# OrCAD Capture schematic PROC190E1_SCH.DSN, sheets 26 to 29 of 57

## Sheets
26 24. HYPERRAM INTERFACE: size C; title: HYPERRAM INTERFACE
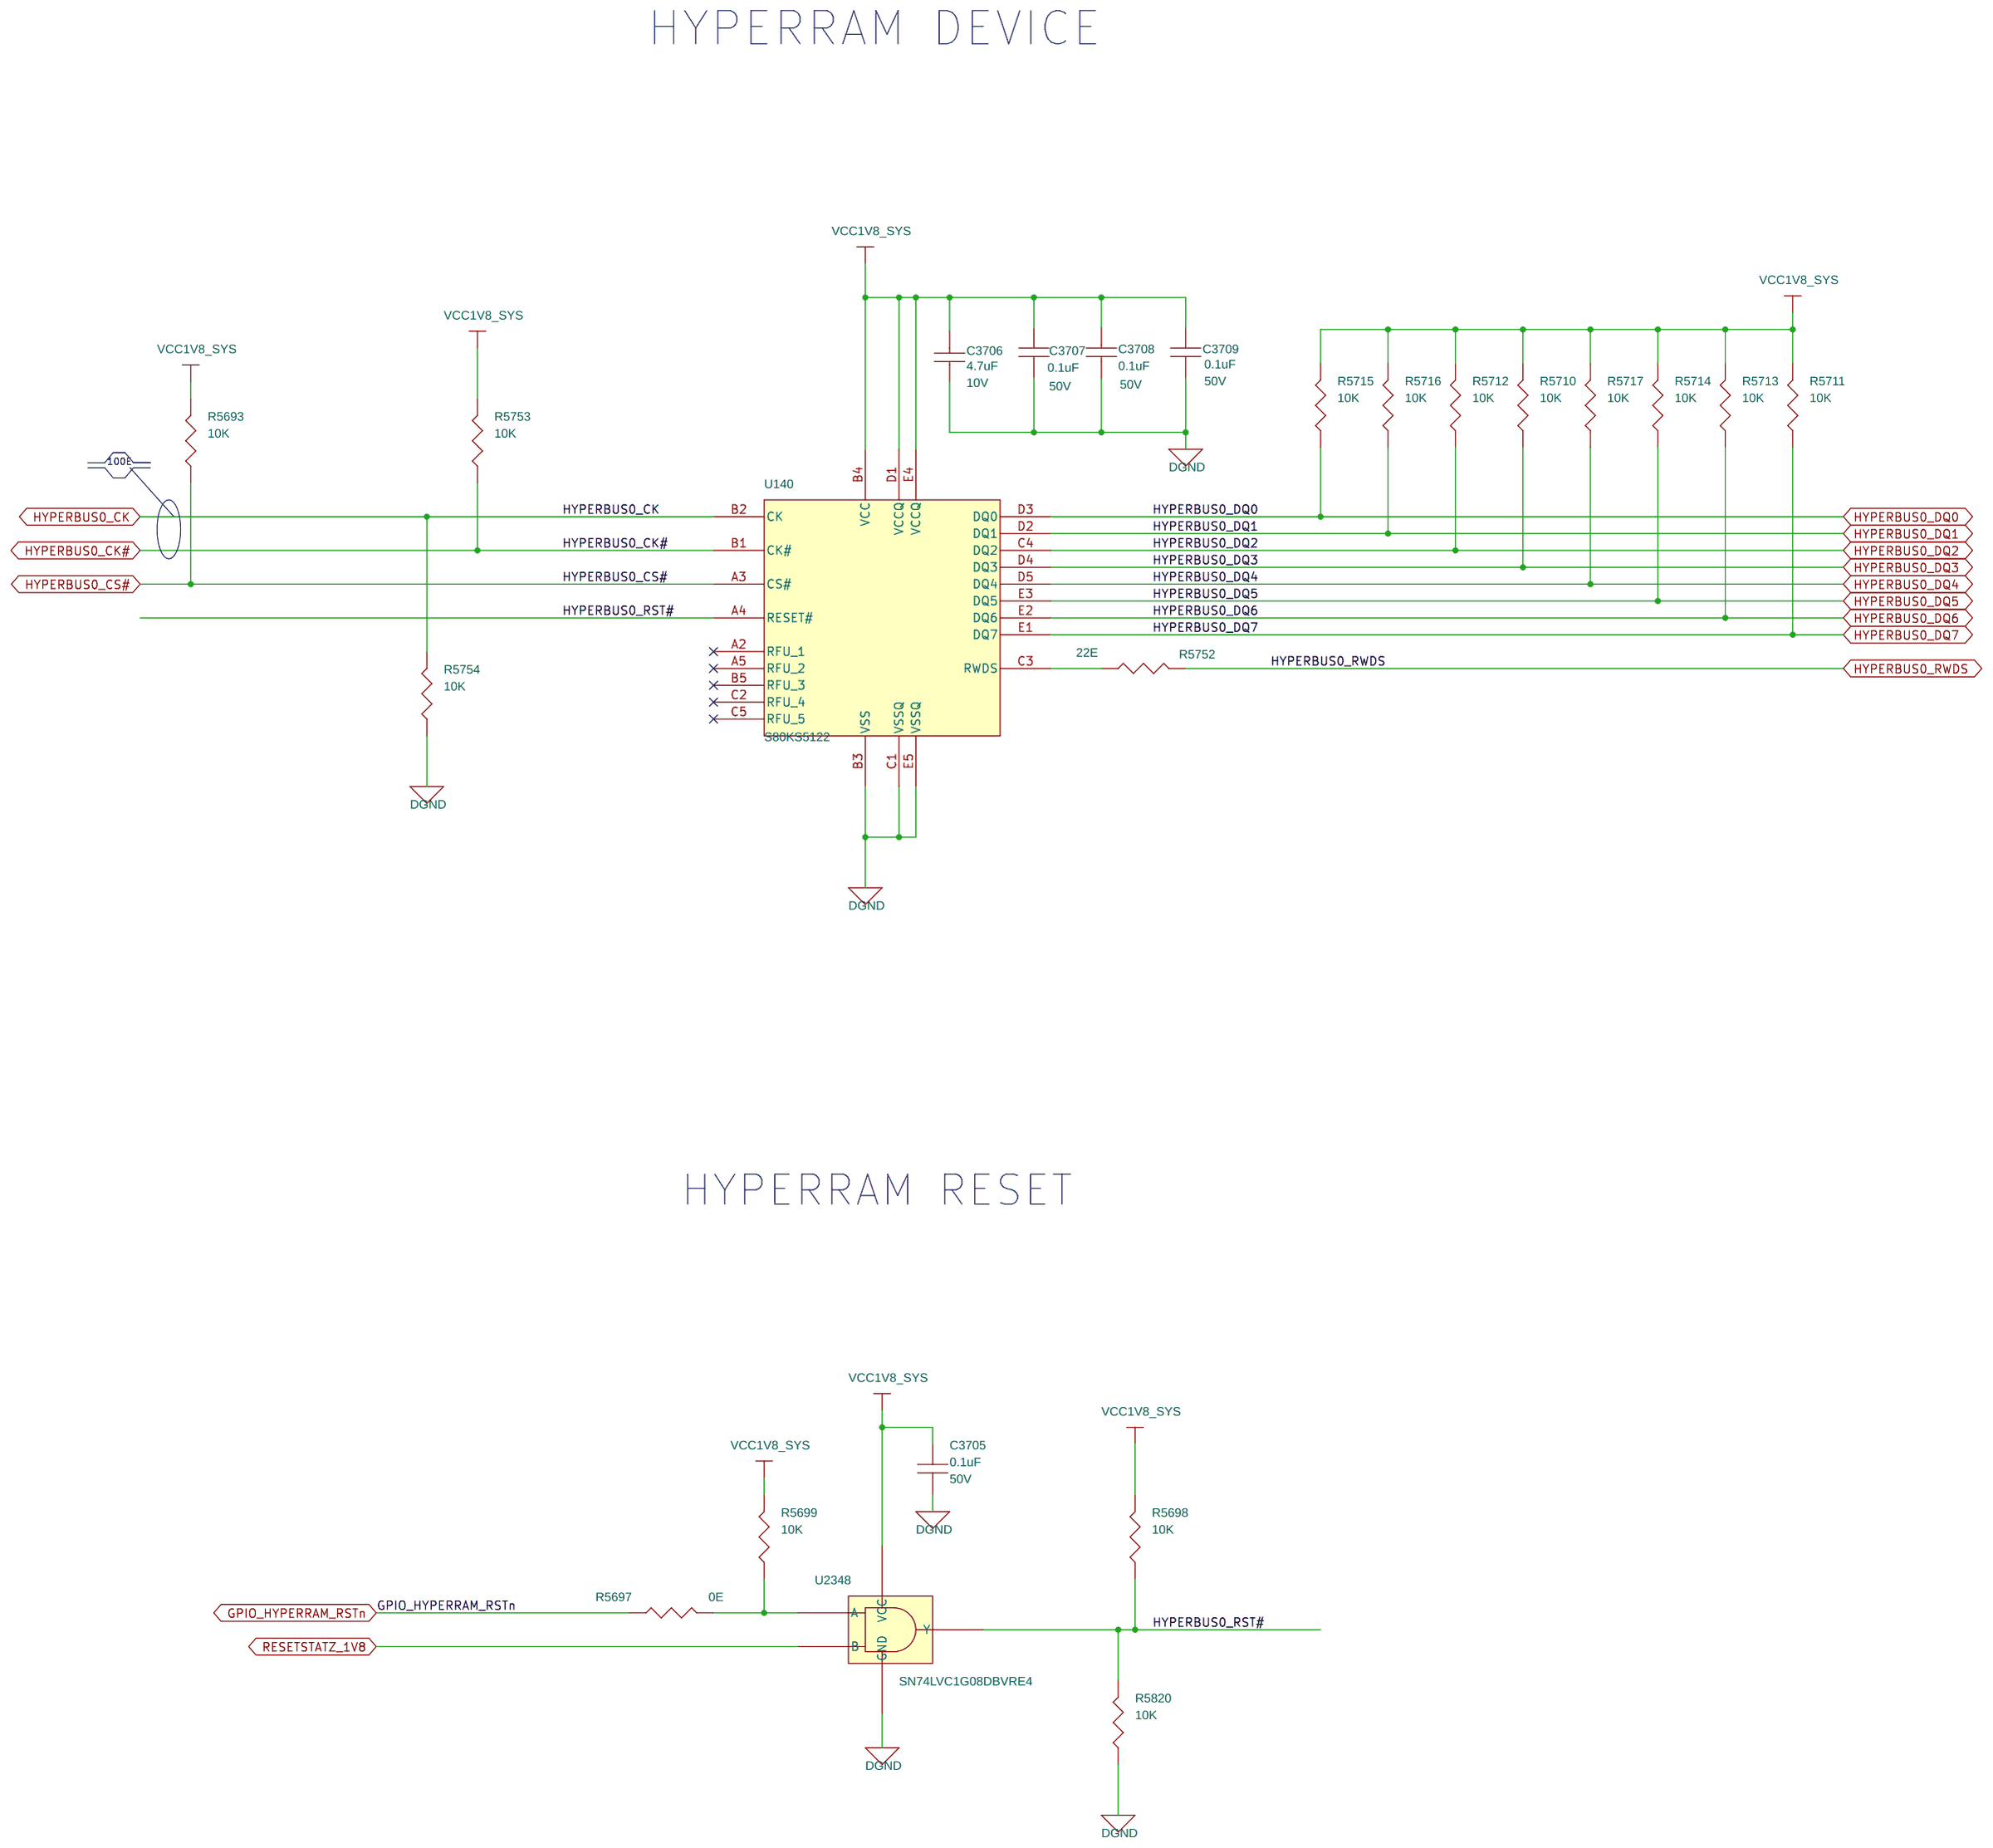
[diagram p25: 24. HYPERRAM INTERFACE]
27 25. OSPI INTERFACE: size C; title: OSPI INTERFACE
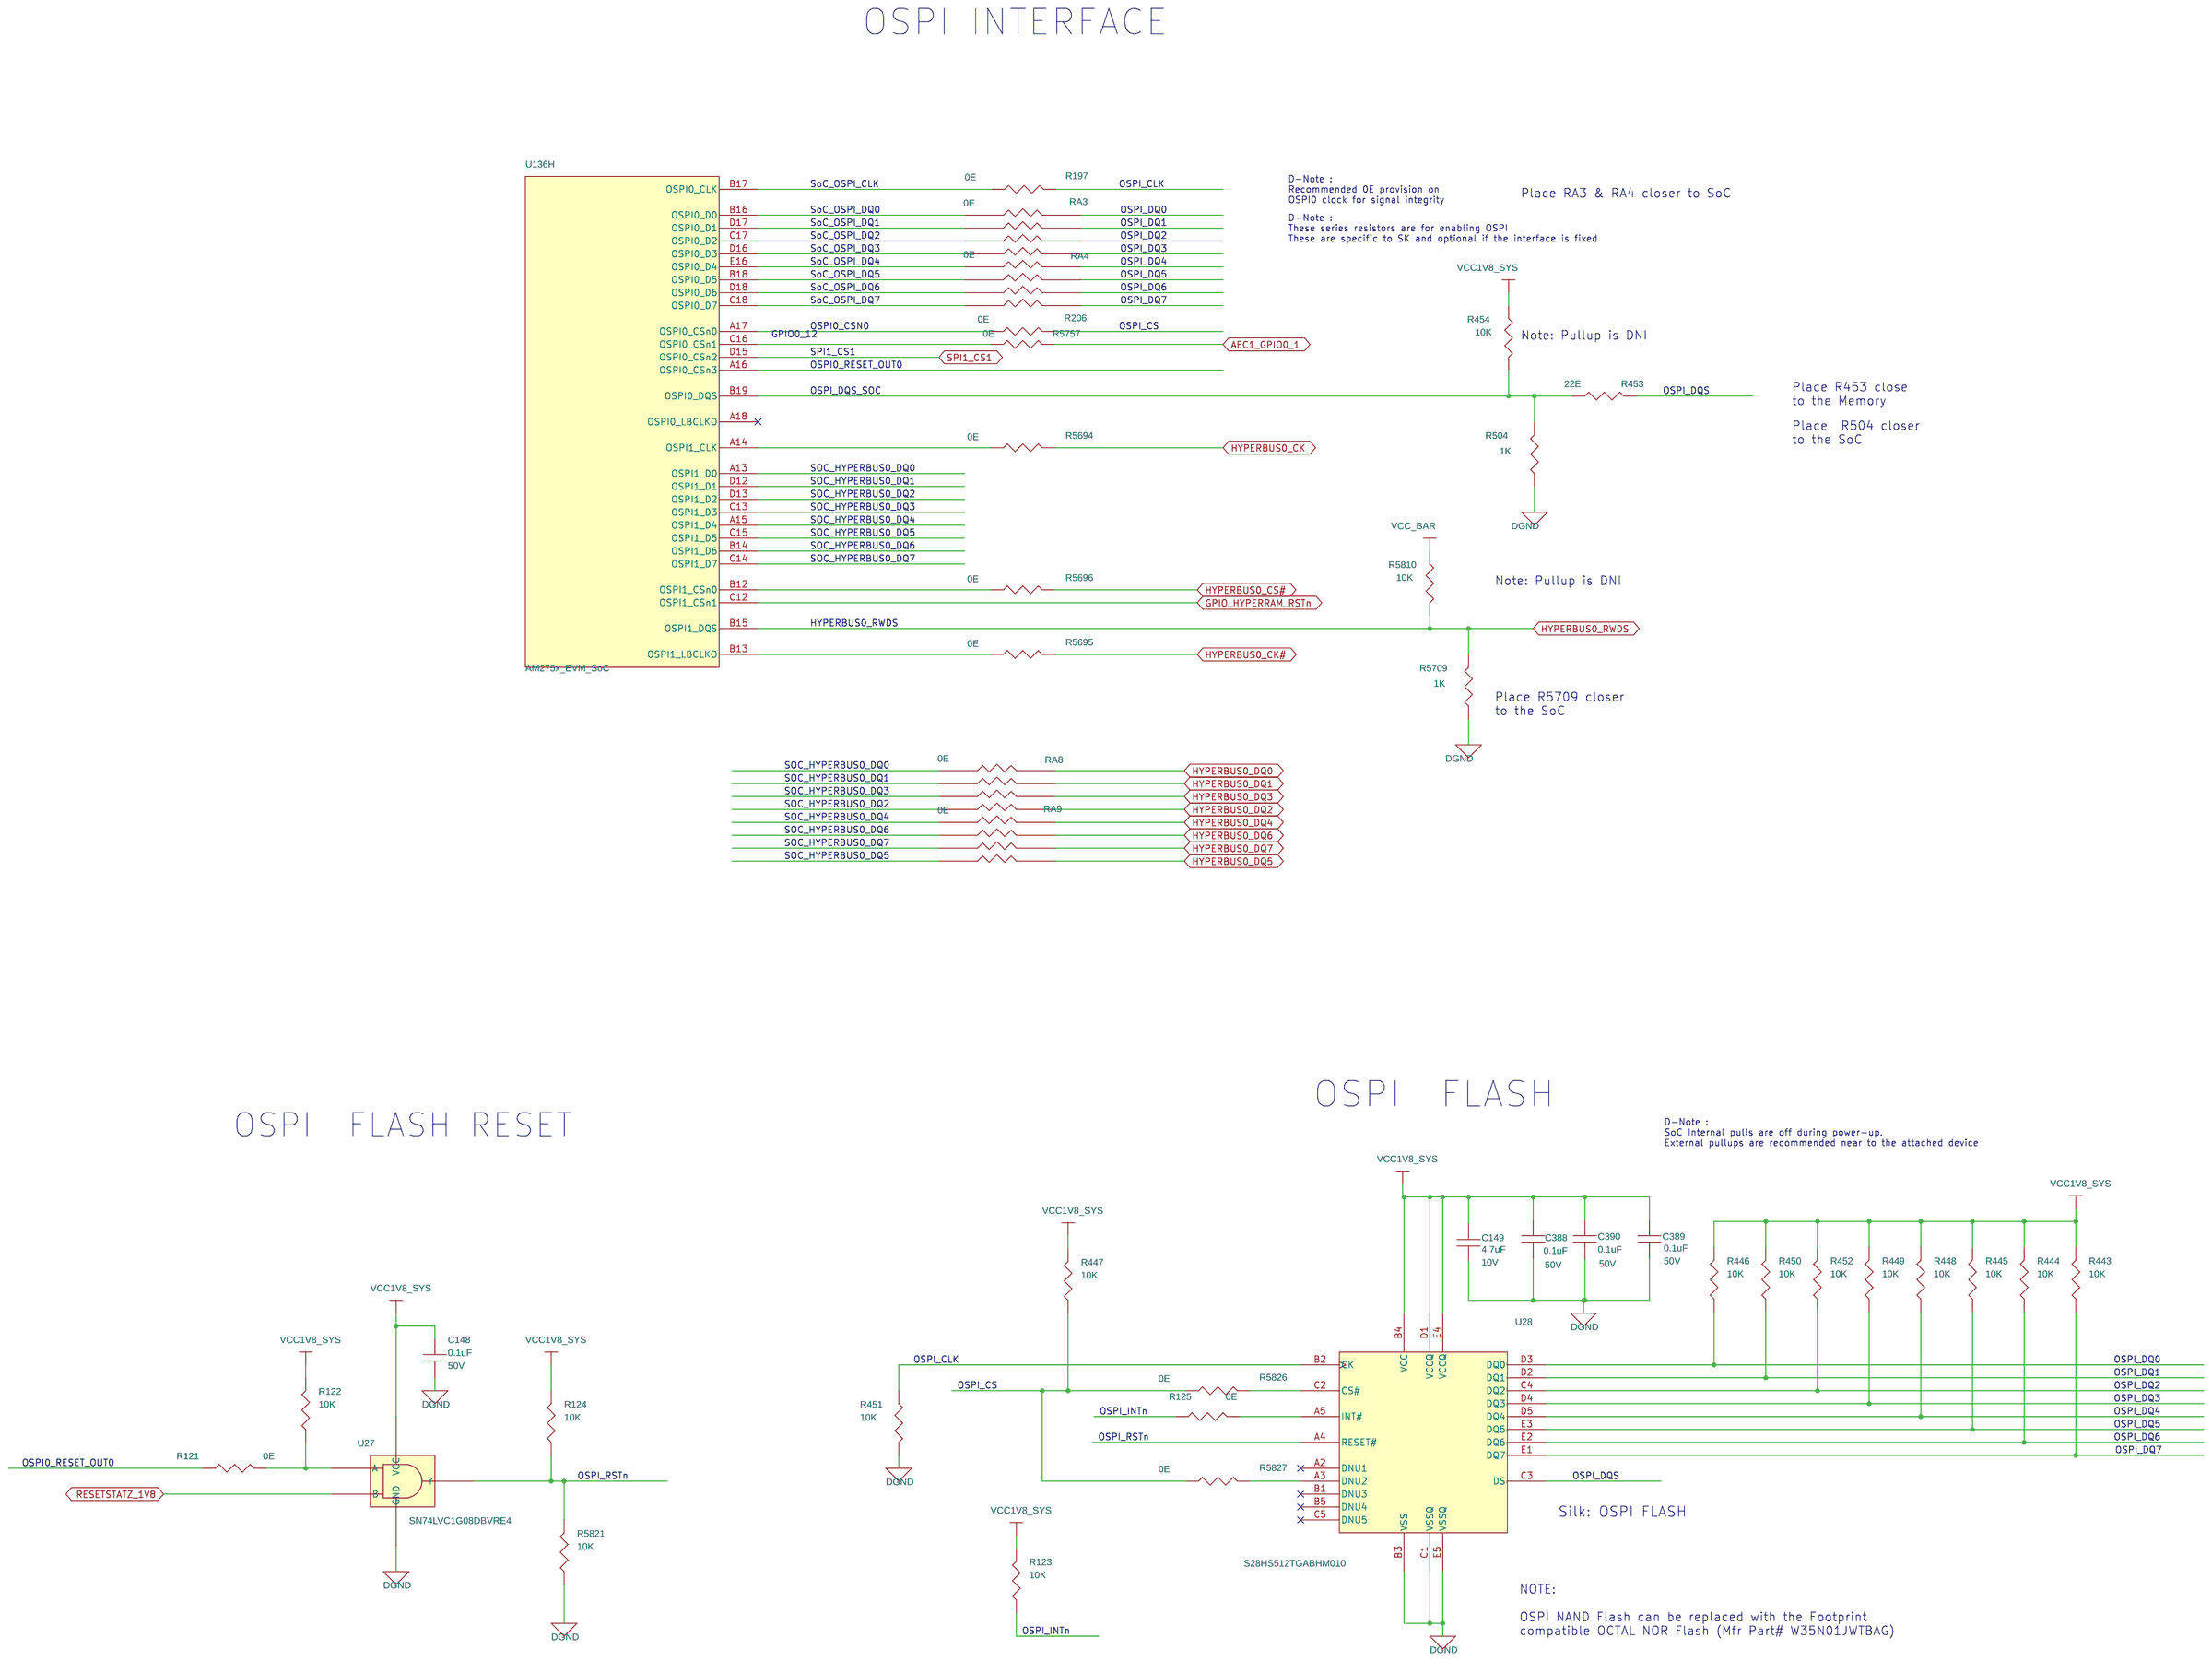
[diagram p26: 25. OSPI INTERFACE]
28 27. eMMC FLASH INTERFACE: size C; title: eMMC  FLASH AND RESET
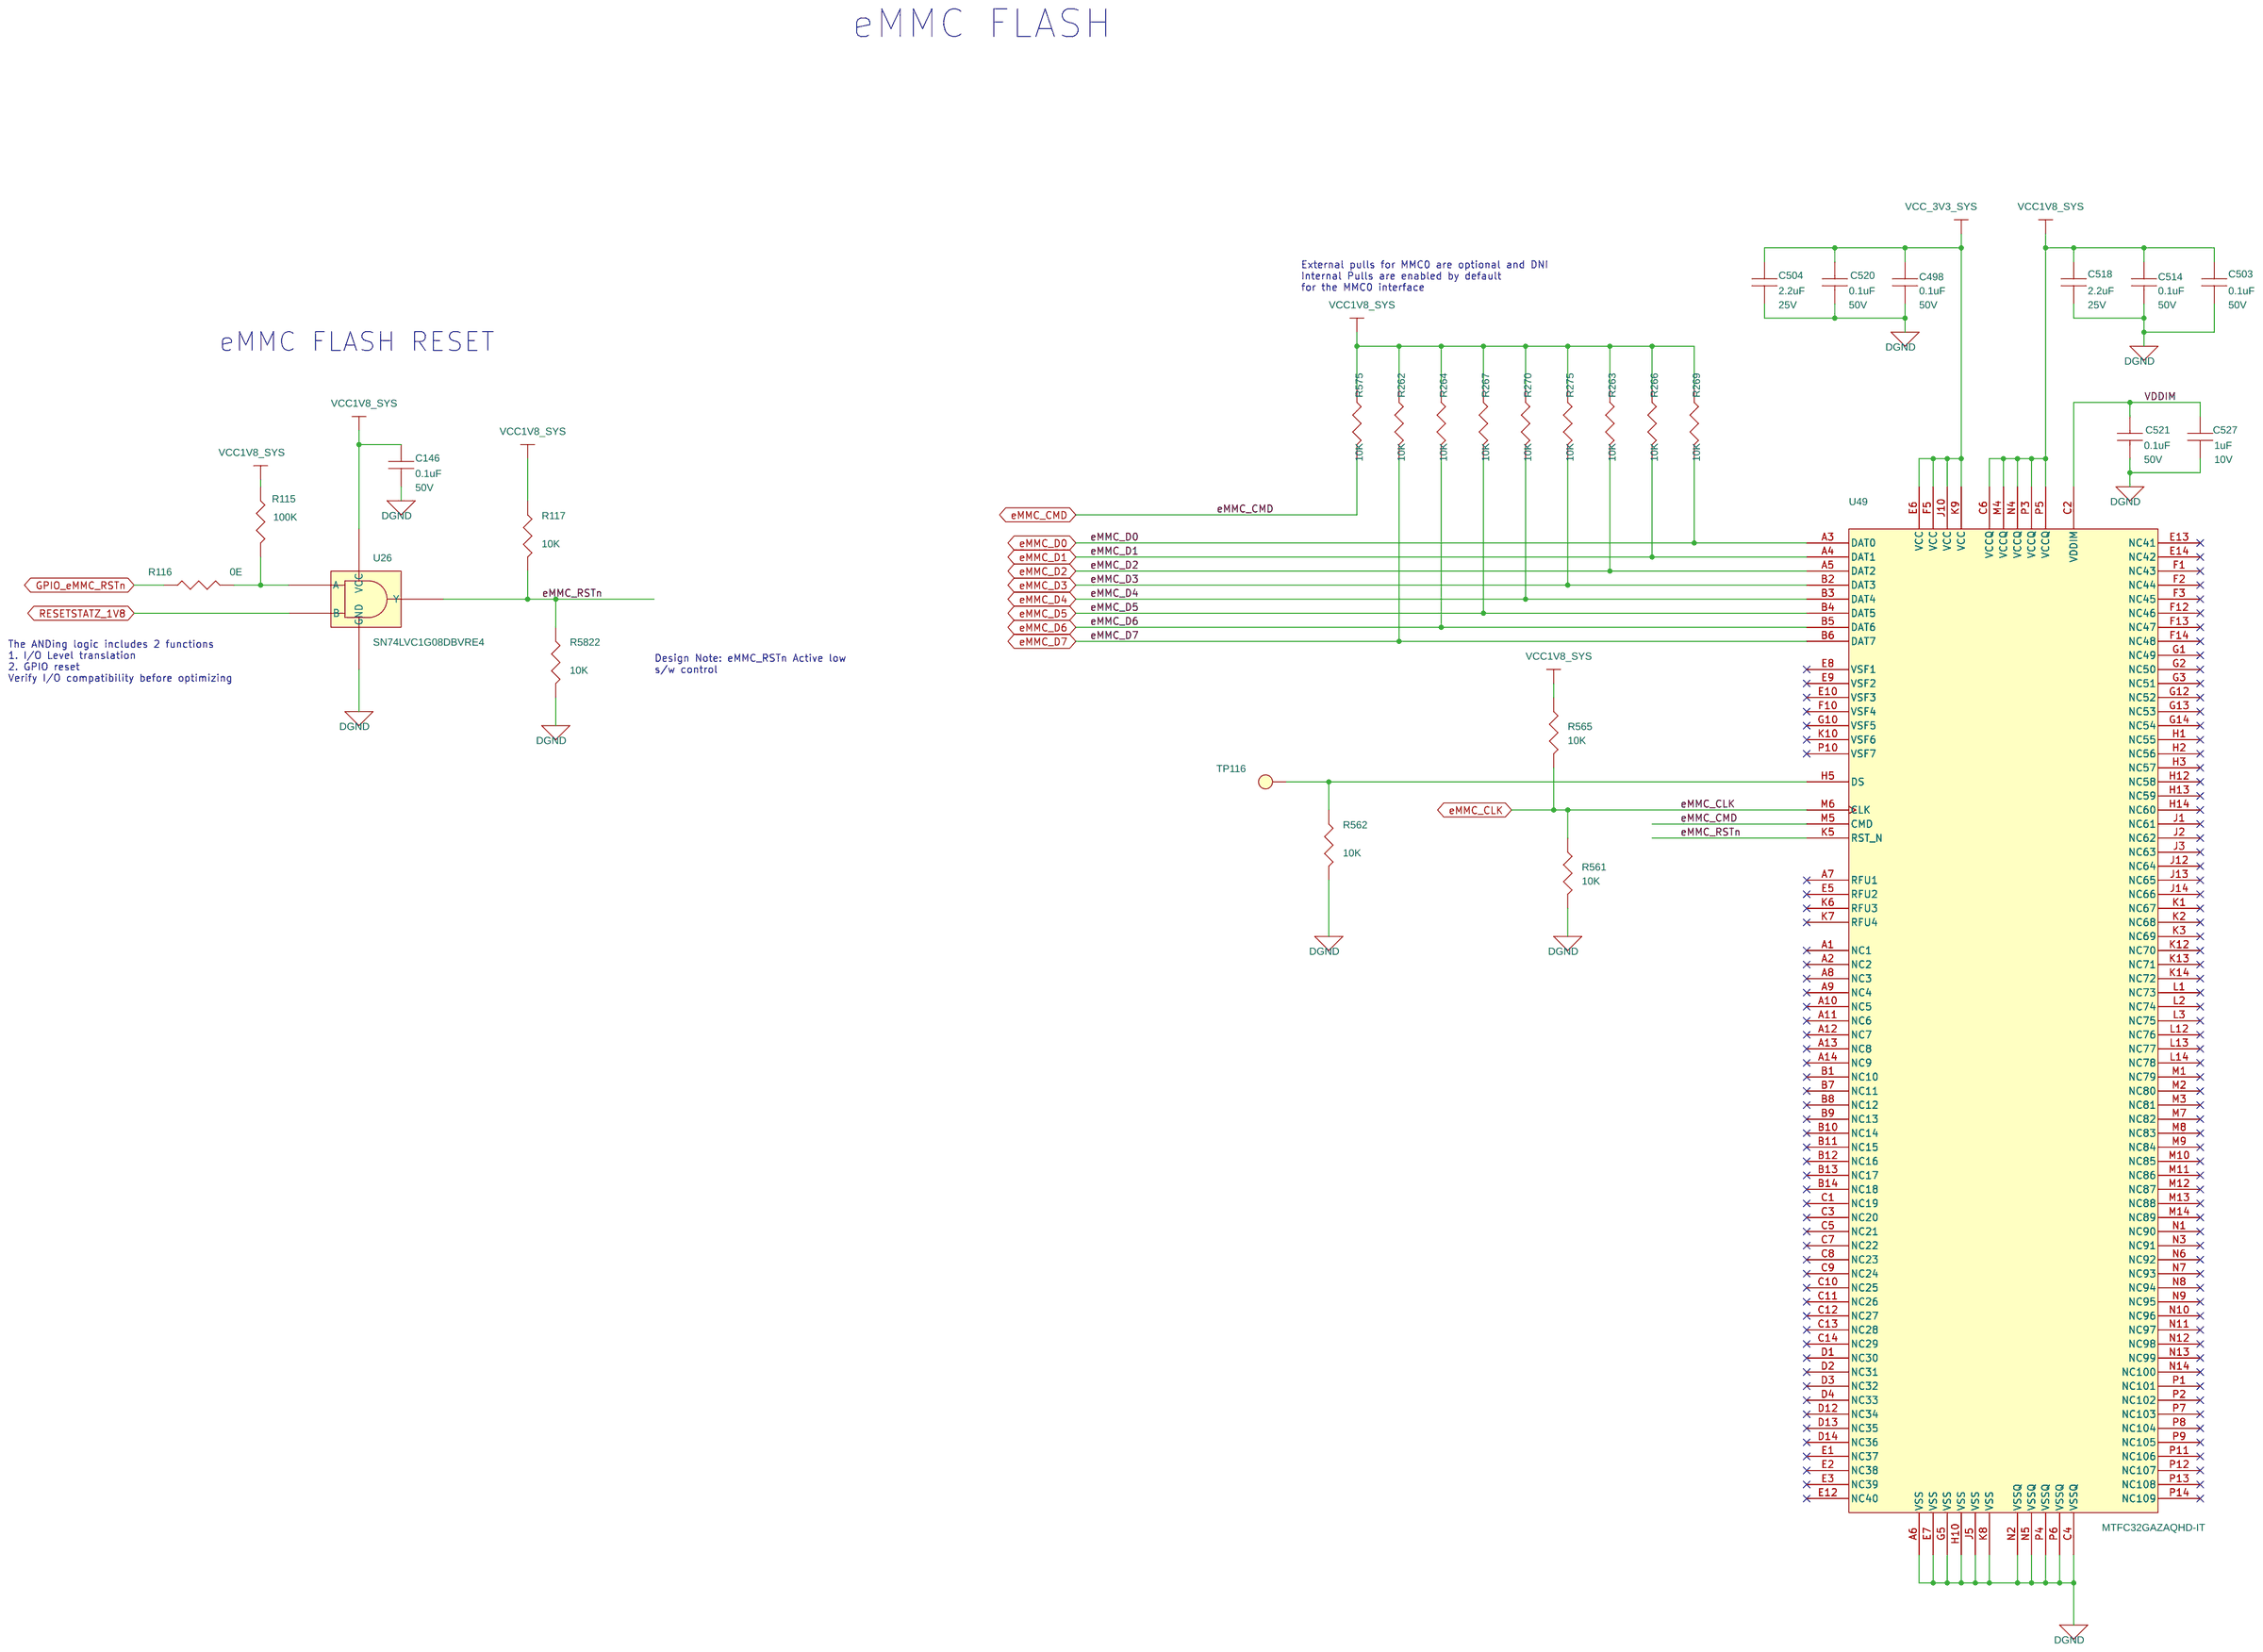
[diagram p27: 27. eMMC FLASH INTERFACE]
29 28. SD CARD INTERFACE: size C; title: SD CARD INTERFACE
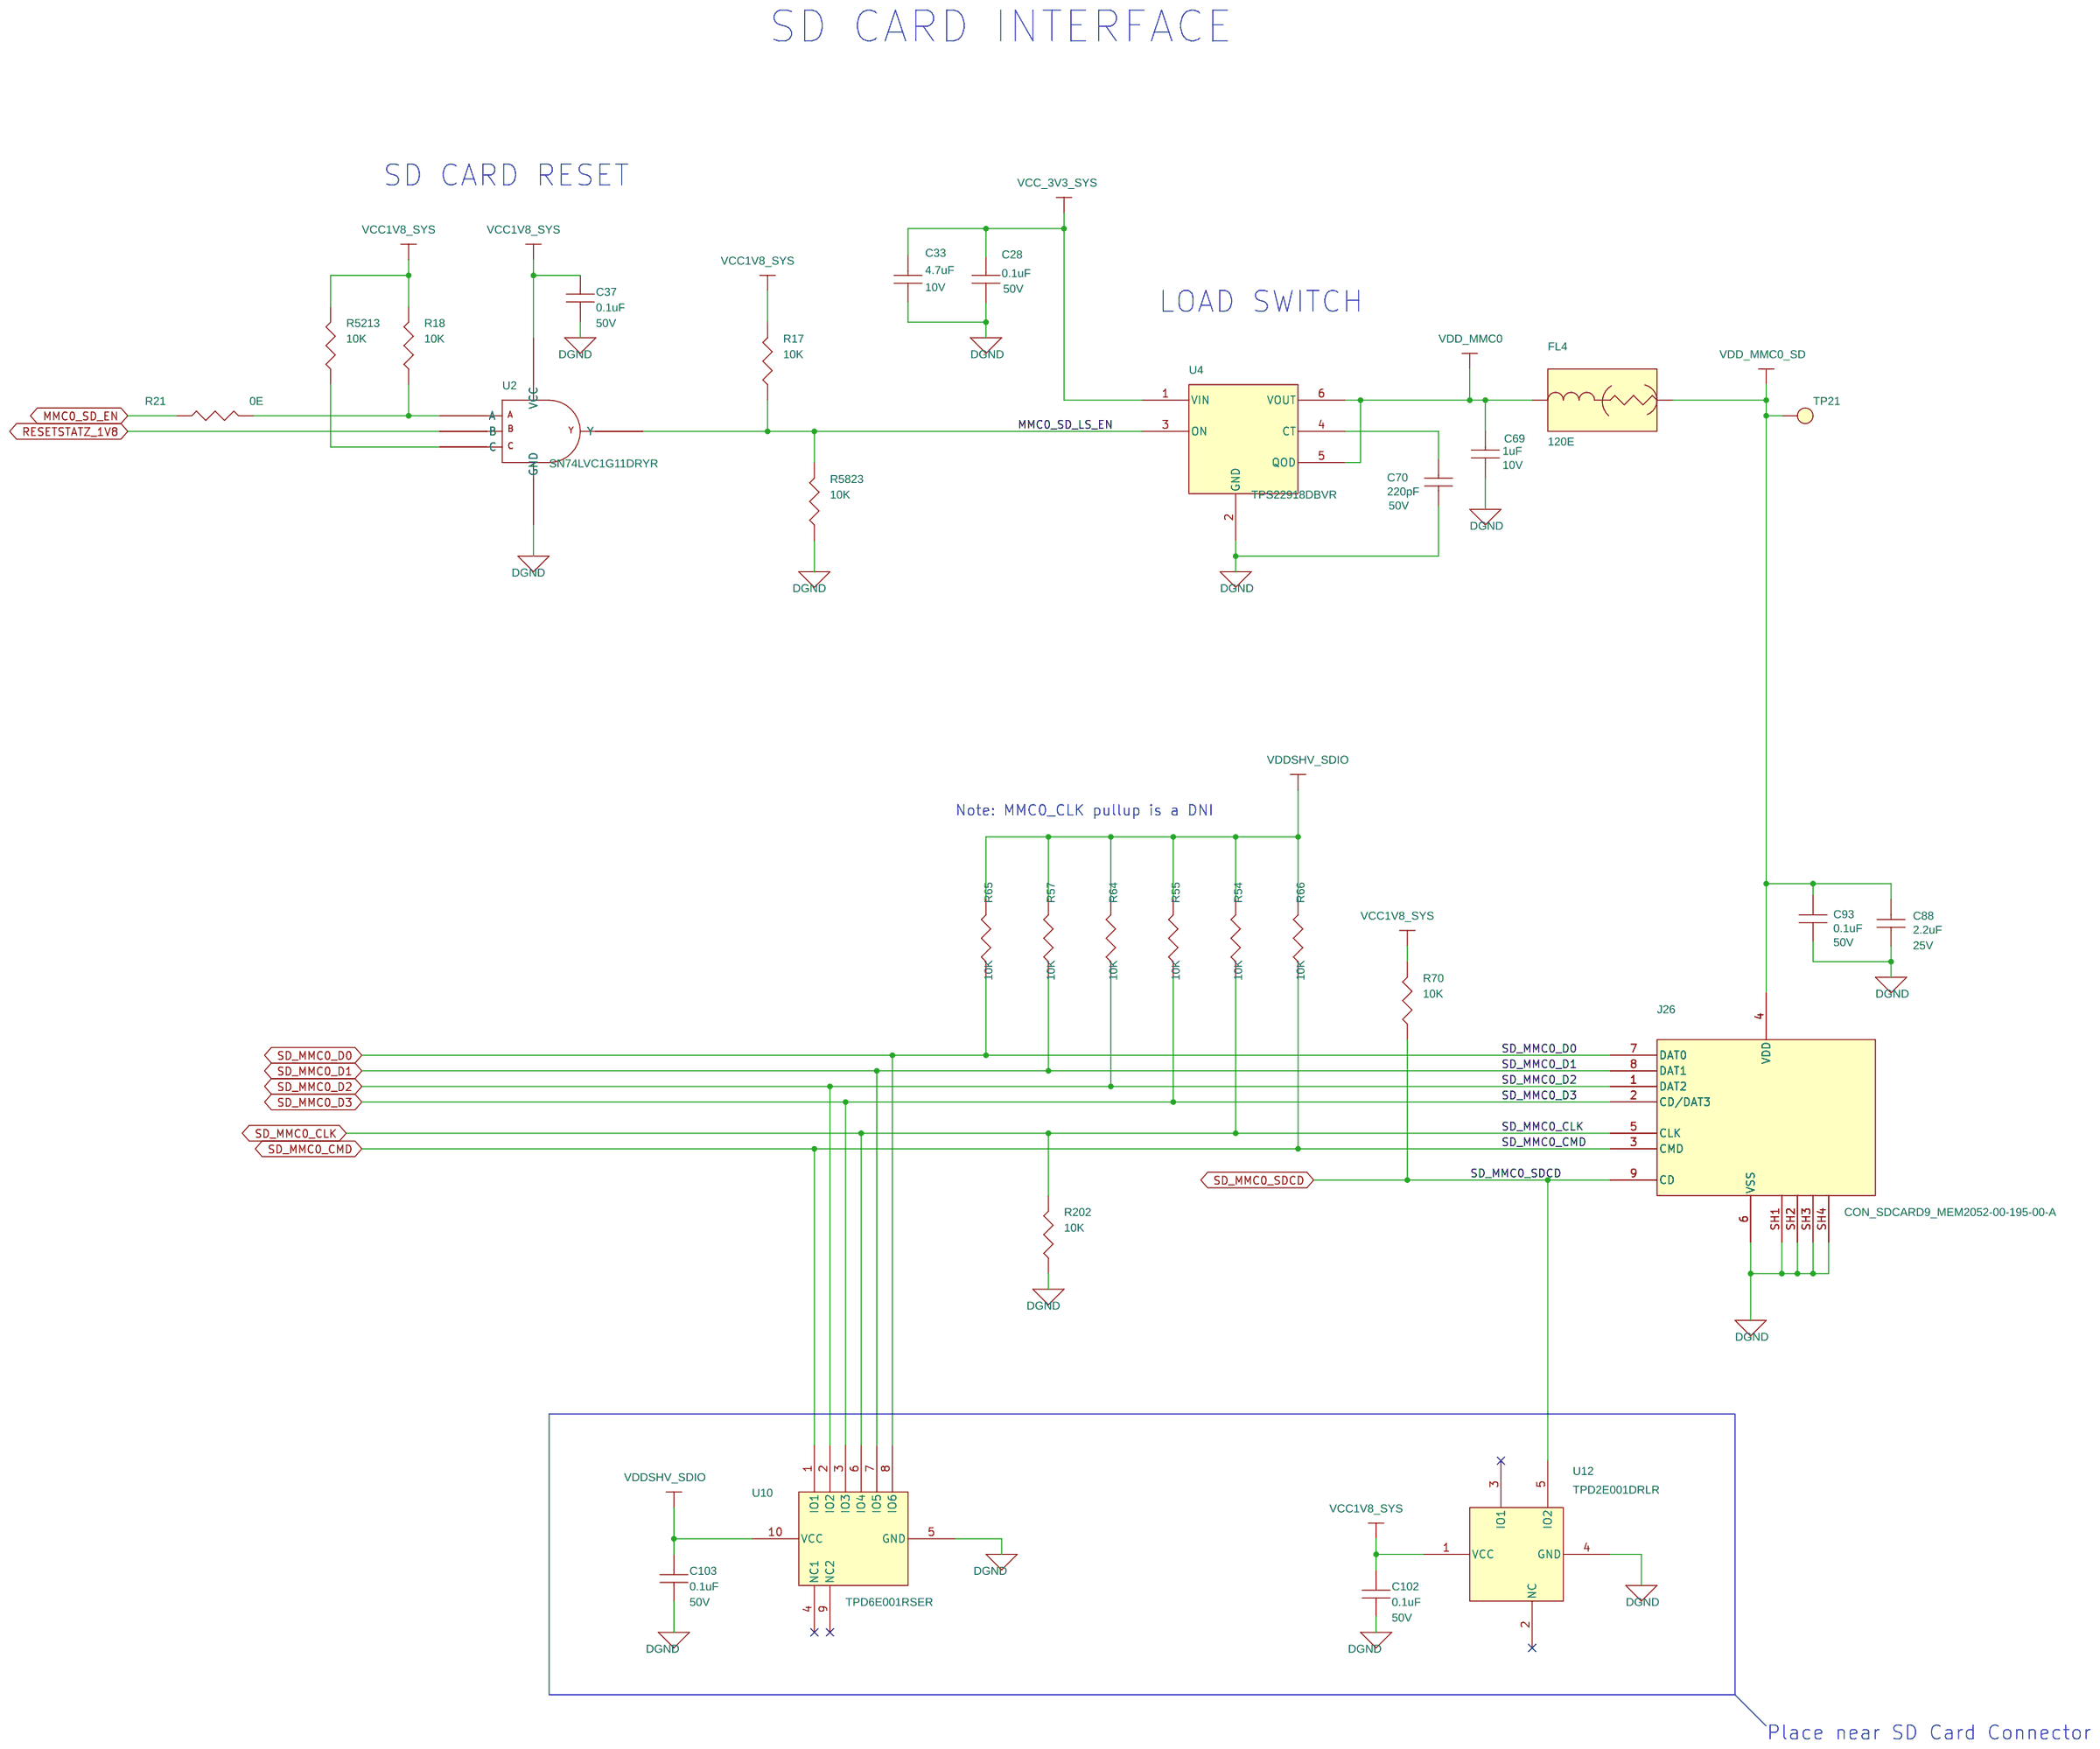
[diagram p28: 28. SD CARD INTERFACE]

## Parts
sheet 19. SOC WKUP & OSC
U136  AM275x_EVM_SoC  [BGA361_31-49_630X630_1-5]  (sections A,B,C,D,E,F,G,H,I,J,K,L,M,N)
sheet 24. HYPERRAM INTERFACE
C3705  0.1uF  [CAP0402_0-75]
C3706  4.7uF  [CAP0402_0-75]
C3707  0.1uF  [CAP0402_0-75]
C3708  0.1uF  [CAP0402_0-75]
C3709  0.1uF  [CAP0402_0-75]
R5693  10K  [RES0201_0-5]
R5697  0E  [RES0201_0-5]
R5698  10K  [RES0201_0-5]
R5699  10K  [RES0201_0-5]
R5710  10K  [RES0201_0-5]
R5711  10K  [RES0201_0-5]
R5712  10K  [RES0201_0-5]
R5713  10K  [RES0201_0-5]
R5714  10K  [RES0201_0-5]
R5715  10K  [RES0201_0-5]
R5716  10K  [RES0201_0-5]
R5717  10K  [RES0201_0-5]
R5752  22E  [RES0402_0-5]
R5753  10K  [RES0201_0-5]
R5754  10K  [RES0201_0-5]
R5820  10K  [RES0201_0-5]
U140  S80KS5122  [BGA24_39-37_240X310_1]
U2348  SN74LVC1G08DBVRE4  [SOT23-5]
sheet 25. OSPI INTERFACE
C148  0.1uF  [CAP0402_0-75]
C149  4.7uF  [CAP0402_0-75]
C388  0.1uF  [CAP0402_0-75]
C389  0.1uF  [CAP0402_0-75]
C390  0.1uF  [CAP0402_0-75]
R121  0E  [RES0201_0-5]
R122  10K  [RES0201_0-5]
R123  10K  [RES0201_0-5]
R124  10K  [RES0201_0-5]
R125  0E  [RES0201_0-5]
R197  0E  [RES0402_0-5]
R206  0E  [RES0402_0-5]
R443  10K  [RES0201_0-5]
R444  10K  [RES0201_0-5]
R445  10K  [RES0201_0-5]
R446  10K  [RES0201_0-5]
R447  10K  [RES0201_0-5]
R448  10K  [RES0201_0-5]
R449  10K  [RES0201_0-5]
R450  10K  [RES0201_0-5]
R451  10K  [RES0201_0-5]
R452  10K  [RES0201_0-5]
R453  22E  [RES0201_0-5]
R454  10K  [RES0201_0-5]
R504  1K  [RES0402_0-5]
R5694  0E  [RES0201_0-5]
R5695  0E  [RES0201_0-5]
R5696  0E  [RES0201_0-5]
R5709  1K  [RES0402_0-5]
R5757  0E  [RES0402_0-5]
R5810  10K  [RES0201_0-5]
R5821  10K  [RES0201_0-5]
R5826  0E  [RES0402_0-5]
R5827  0E  [RES0402_0-5]
RA3  0E  [RESA_EXB_0201-4_0-5]
RA4  0E  [RESA_EXB_0201-4_0-5]
RA8  0E  [RESA_EXB_0201-4_0-5]
RA9  0E  [RESA_EXB_0201-4_0-5]
U27  SN74LVC1G08DBVRE4  [SOT23-5]
U28  S28HS512TGABHM010  [BGA24_39-37_240X310_1]
sheet 27. eMMC FLASH INTERFACE
C146  0.1uF  [CAP0402_0-75]
C498  0.1uF  [CAP0402_0-75]
C503  0.1uF  [CAP0402_0-75]
C504  2.2uF  [CAP0402_0-75]
C514  0.1uF  [CAP0402_0-75]
C518  2.2uF  [CAP0402_0-75]
C520  0.1uF  [CAP0402_0-75]
C521  0.1uF  [CAP0402_0-75]
C527  1uF  [CAP0201_0-5]
R115  100K  [RES0201_0-5]
R116  0E  [RES0201_0-5]
R117  10K  [RES0201_0-5]
R262  10K  [RES0201_0-5]
R263  10K  [RES0201_0-5]
R264  10K  [RES0201_0-5]
R266  10K  [RES0201_0-5]
R267  10K  [RES0201_0-5]
R269  10K  [RES0201_0-5]
R270  10K  [RES0201_0-5]
R275  10K  [RES0201_0-5]
R561  10K  [RES0201_0-5]
R562  10K  [RES0201_0-5]
R565  10K  [RES0201_0-5]
R575  10K  [RES0201_0-5]
R5822  10K  [RES0201_0-5]
TP116  TP20_SMD  [TP20_SMD]
U26  SN74LVC1G08DBVRE4  [SOT23-5]
U49  MTFC32GAZAQHD-IT  [VFBGA153_19-68_460X520_0-9]
sheet 28. SD CARD INTERFACE
C28  0.1uF  [CAP0402_0-75]
C33  4.7uF  [CAP0402_0-75]
C37  0.1uF  [CAP0402_0-75]
C69  1uF  [CAP0201_0-5]
C70  220pF  [CAP0402_0-75]
C88  2.2uF  [CAP0402_0-75]
C93  0.1uF  [CAP0402_0-75]
C102  0.1uF  [CAP0402_0-75]
C103  0.1uF  [CAP0402_0-75]
FL4  120E  [EMIFIL_BLM15A_0402_0-6]
J26  CON_SDCARD9_MEM2052-00-195-00-A  [CON_SD9_MEM2052-00-195-00_S_R_S_2]
R17  10K  [RES0201_0-5]
R18  10K  [RES0201_0-5]
R21  0E  [RES0201_0-5]
R54  10K  [RES0201_0-5]
R55  10K  [RES0201_0-5]
R57  10K  [RES0201_0-5]
R64  10K  [RES0201_0-5]
R65  10K  [RES0201_0-5]
R66  10K  [RES0201_0-5]
R70  10K  [RES0201_0-5]
R202  10K  [RES0201_0-5]
R5213  10K  [RES0201_0-5]
R5823  10K  [RES0201_0-5]
TP21  TP20_SMD  [TP20_SMD]
U2  SN74LVC1G11DRYR  [SON6_SN74LVC2G17_40X60_0-6]
U4  TPS22918DBVR  [SOT23-6]
U10  TPD6E001RSER  [UQFN10_19-68_80X60_0-6]
U12  TPD2E001DRLR  [SOT553-5_0-6]

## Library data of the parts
U136 = AM275X_EVM_SOC_BGA361: IC AM275x EVM SoC BGA361; Chkd/date: PRADEEP/220524; Crtd /date: SHANKARI/210524; Custom_Duty: NA; Customs_HS_Code: NA; Distributor_name: NA; Distributor_part_number: NA; Height: 1.42MM; Library Ref: AM275x_EVM_SoC_BGA361; Mfr_name: NA; Mistral Part No: 141324050006; Package: BGA361; Part_type: ICS\DIGITAL\FPGA; Project: AM275x_EVM; Remarks: FP NEED TO CHECK WITH MANUFACTURE AND CUSTOMER; RoHS: NA; Temperature: NA; Tolerance: NA; Voltage: NA; Wattage: NA; Weight: NA; Datasheet: Y:\MIS_DATABASE\DATASHEETS\ICS\INTERFACE\AM275x_EVM_SoC.PDF
C28 C37 C93 C102 C103 C146 C148 C388-C390 C498 C503 C514 C520 C521 C3705 C3707-C3709 = CAP: CAP CERAMIC 0.1uF 50V 10% X7R AUTO 0402; Alt_Mfr_name: YAGEO AMERICA; Alt_Mfr_part_number: CC0402KRX5R8BB104; Chkd/date: MANIRAJA/250221; Crtd /date: ALVY/240221; Custom_Duty: 15%; Customs_HS_Code: 85322990; Distributor_name: MOUSER; Distributor_part_number: 81-GRT155R71H104KE1D; Footprint Path: Y:\MIS_DATABASE\Library\ALTIUM_TOOL\PCB_FOOTPRINTS\Altium_Footprint_Lib.PcbLib; Height: 0.55MM; Library Path: Y:\MIS_DATABASE\Library\ALTIUM_TOOL\SCHEMATICS_PARTS\MS_DISCRETE_Library.schlib; Mfr_name: MURATA; Mfr_part_number: GRT155R71H104KE01D; Mistral Part No: 120019030005-R; Package: 0402; Part_type: CAPACITORS\CERAMIC; Project: TI_DRA821 SK EVM BRD; RoHS: RoHS; Temperature: -55°C+125°C; Tolerance: 10%; Voltage: 50V; Wattage: NA; Weight: NA; Datasheet: Y:\MIS_DATABASE\DATASHEETS\CAPACITORS\GRT155R71H104KE01.PDF
C33 C149 C3706 = CAP: CAP CERAMIC 4.7uF 10V 20% X5R AUTO 0402; Chkd/date: MANIRAJA/250221; Crtd /date: ALVY/240221; Custom_Duty: 15%; Customs_HS_Code: 85322990; Distributor_name: MOUSER; Distributor_part_number: 81-GRT155R61A475ME13; Footprint Path: Y:\MIS_DATABASE\Library\ALTIUM_TOOL\PCB_FOOTPRINTS\Altium_Footprint_Lib.PcbLib; Height: 0.65MM; Library Path: Y:\MIS_DATABASE\Library\ALTIUM_TOOL\SCHEMATICS_PARTS\MS_DISCRETE_Library.schlib; Mfr_name: MURATA; Mfr_part_number: GRT155R61A475ME13D; Mistral Part No: 120021020032-R; Package: 0402; Part_type: CAPACITORS\CERAMIC; Project: TI_DRA821 SK EVM BRD; RoHS: RoHS; Temperature: -55°C+85°C; Tolerance: 20%; Voltage: 10V; Wattage: NA; Weight: 1.5mg; Datasheet: Y:\MIS_DATABASE\DATASHEETS\CAPACITORS\GRT155R61A475ME13.PDF
R17 R18 R54 R55 R57 R64-R66 R70 R117 R122-R124 R202 R262-R264 R266 R267 R269 R270 R275 R443-R452 R454 R561 R562 R565 R575 R5213 R5693 R5698 R5699 R5710-R5717 R5753 R5754 R5810 R5820-R5823 = RESISTOR: RES 10K 1/20W 5% 0201; Chkd/date: MANIRAJA/050517; Crtd /date: MANIRAJA/050517; Custom_Duty: 15%; Customs_HS_Code: 85332119; Distributor_name: DIGIKEY; Distributor_part_number: 311-10KNCT-ND; Footprint Path: Y:\MIS_DATABASE\Library\ALTIUM_TOOL\PCB_FOOTPRINTS\Altium_Footprint_Lib.PcbLib; Height: 0.26MM; Library Path: Y:\MIS_DATABASE\Library\ALTIUM_TOOL\SCHEMATICS_PARTS\MS_DISCRETE_Library.schlib; Mfr_name: YAGEO AMERICA; Mfr_part_number: RC0201JR-0710KL; Mistral Part No: 110010070051-R; Package: 0201; Part_type: RESISTORS\FIXED; Project: GOLDEN-I LITE; RoHS: RoHS; Temperature: -55°C+125°C; Tolerance: 5%; Voltage: NA; Wattage: 1/20W; Weight: 0.17mg; Datasheet: Y:\MIS_DATABASE\DATASHEETS\RESISTORS\RCXXXXL-SER_MAR18.PDF
R21 R116 R121 R125 R5697 = RESISTOR: RES 0E 1/20W 5% 0201; Chkd/date: NAVEED/301214; Crtd /date: MUDDU/120710; Custom_Duty: 15%; Customs_HS_Code: 85332119; Distributor_name: DIGIKEY; Distributor_part_number: 311-0.0NCT-ND; Footprint Path: Y:\MIS_DATABASE\Library\ALTIUM_TOOL\PCB_FOOTPRINTS\Altium_Footprint_Lib.PcbLib; Height: 0.26MM; Library Path: Y:\MIS_DATABASE\Library\ALTIUM_TOOL\SCHEMATICS_PARTS\MS_DISCRETE_Library.schlib; Mfr_name: YAGEO AMERICA; Mfr_part_number: RC0201JR-070RL; Mistral Part No: 110010070067-R; Package: 0201; Part_type: RESISTORS\FIXED; Project: PB_BUGBASE; RoHS: RoHS; Temperature: -55°C+125°C; Tolerance: 5%; Voltage: NA; Wattage: 1/20W; Weight: 0.17mg; Datasheet: Y:\MIS_DATABASE\DATASHEETS\RESISTORS\RCXXXXL-SER_MAR18.PDF
R5752 = RESISTOR: RES 22E 1/10W 5% 0402; Chkd/date: VASANTHA/060117; Crtd /date: MAZHAR/120505; Custom_Duty: 15%; Customs_HS_Code: 85332119; Distributor_name: DIGIKEY; Distributor_part_number: P22JCT-ND; Footprint Path: Y:\MIS_DATABASE\Library\ALTIUM_TOOL\PCB_FOOTPRINTS\Altium_Footprint_Lib.PcbLib; Height: 0.40MM; Library Path: Y:\MIS_DATABASE\Library\ALTIUM_TOOL\SCHEMATICS_PARTS\MS_DISCRETE_Library.schlib; Mfr_name: PANASONIC-ECG; Mfr_part_number: ERJ-2GEJ220X; Mistral Part No: 110009030515-R; Package: 0402; Part_type: RESISTORS\FIXED; Project: EPDA_CORE; RoHS: RoHS; Temperature: -55°C+155°C; Tolerance: 5%; Voltage: NA; Wattage: 1/10W; Weight: 0.8mg; Datasheet: Y:\MIS_DATABASE\DATASHEETS\RESISTORS\PAN-ERJSER_NOV17.PDF
U140 = S80KS5122GABHM_BGA24: IC 512MBIT FLASH MEMORY BGA24; Chkd/date: PRADEEP/200524; Crtd /date: SHANKARI/200524; Custom_Duty: 15%; Customs_HS_Code: 85423100; Distributor_name: DIGYKEY; Distributor_part_number: 448-S80KS5122GABHM020-ND; Footprint Path: Y:\MIS_DATABASE\Library\ALTIUM_TOOL\PCB_FOOTPRINTS\Altium_Footprint_Lib.PcbLib; Height: 1.00MM; Library Path: Y:\MIS_DATABASE\Library\ALTIUM_TOOL\SCHEMATICS_PARTS\MS_MISCPOWER_Library.schlib; Mfr_name: INFINEON TECHNOLOGIES; Mfr_part_number: S80KS5122GABHM020; Mistral Part No: 141124050003-R; Package: BGA24; Part_type: ICS\DIGITAL\MEMORY; Project: AM275x_EVM; RoHS: RoHS; Temperature: -40°C+125°C; Tolerance: NA; Voltage: NA; Wattage: NA; Weight: NA; Datasheet: Y:\MIS_DATABASE\DATASHEETS\ICS\INTERFACE\S80KS5122.PDF
U26 U27 U2348 = SN74LVC1G08DBVRE4_SOT23-5: IC SINGLE 2-INPUT POSITIVE AND GATE SOT23-5; Chkd/date: SUHAS/221010; Crtd /date: USMAN/151008; Custom_Duty: 15%; Customs_HS_Code: 85423100; Distributor_name: DIGIKEY; Distributor_part_number: SN74LVC1G08DBVRE4-ND; Height: 1.45MM; Mfr_name: TEXAS INSTRUMENTS; Mistral Part No: 141009060026-R; Part_type: ICS\DIGITAL\GATES; Project: KHAN_MAIN; RoHS: Sb/ Br FREE; Temperature: -40°C+85°C; Datasheet: Y:\MIS_DATABASE\DATASHEETS\ICS\DIGITAL\GATES\SN74LVC1G08.PDF
R197 R206 R5826 R5827 = RESISTOR: RES 0E 1/10W JUMPER 0402; Chkd/date: VASANTHA/061216; Crtd /date: NAVEED/201014; Custom_Duty: 15%; Customs_HS_Code: 85332119; Distributor_name: DIGIKEY; Distributor_part_number: P0.0JCT-ND; Footprint Path: Y:\MIS_DATABASE\Library\ALTIUM_TOOL\PCB_FOOTPRINTS\Altium_Footprint_Lib.PcbLib; Height: 0.40MM; IBISSP_MODLES: VALUE REPEATING 2 TIME; Library Path: Y:\MIS_DATABASE\Library\ALTIUM_TOOL\SCHEMATICS_PARTS\MS_DISCRETE_Library.schlib; Mfr_name: PANASONIC-ECG; Mfr_part_number: ERJ-2GE0R00X; Mistral Part No: 110018030052-R; Package: 0402; Part_type: RESISTORS\FIXED; Project: AEGIS POM; RoHS: RoHS; SIGNAL_MODEL: RESISTOR_RES0402_0-5_0E_0E; Temperature: -55°C+155°C; Tolerance: NA; Voltage: NA; Wattage: 1/10W; Weight: 0.8mg; Datasheet: Y:\MIS_DATABASE\DATASHEETS\RESISTORS\PAN-ERJSER_NOV17.PDF
R453 = RESISTOR: RES 22E 1/20W 5% 0201; Chkd/date: ALVY/210122; Crtd /date: TAMILARASU/210122; Custom_Duty: 15%; Customs_HS_Code: 85332119; Distributor_name: DIGIKEY; Distributor_part_number: 541-22AGCT-ND; Footprint Path: Y:\MIS_DATABASE\Library\ALTIUM_TOOL\PCB_FOOTPRINTS\Altium_Footprint_Lib.PcbLib; Height: 0.28MM; Library Path: Y:\MIS_DATABASE\Library\ALTIUM_TOOL\SCHEMATICS_PARTS\MS_DISCRETE_Library.schlib; Mfr_name: VISHAY; Mfr_part_number: CRCW020122R0JNED; Mistral Part No: 110022010021-R; Package: 0201; Part_type: RESISTORS\FIXED; Project: DLRL DIGITAL RECEIVER_BRD; RoHS: RoHS; SIGNAL_MODEL: RESISTOR_RES0201_0-5_22E_1%_22E_1%; Temperature: -55°C+155°C; Tolerance: 5%; Voltage: NA; Wattage: 1/20W; Weight: 0.17mg; Datasheet: Y:\MIS_DATABASE\DATASHEETS\RESISTORS\CRCW0201.PDF
R504 R5709 = RESISTOR: RES 1K 1/10W 5% 0402; Chkd/date: VASANTHA/201216; Crtd /date: MAZHAR/230805; Custom_Duty: 15%; Customs_HS_Code: 85332119; Distributor_name: DIGIKEY; Distributor_part_number: P1.0KJCT-ND; Footprint Path: Y:\MIS_DATABASE\Library\ALTIUM_TOOL\PCB_FOOTPRINTS\Altium_Footprint_Lib.PcbLib; Height: 0.40MM; Library Path: Y:\MIS_DATABASE\Library\ALTIUM_TOOL\SCHEMATICS_PARTS\MS_DISCRETE_Library.schlib; Mfr_name: PANASONIC-ECG; Mfr_part_number: ERJ-2GEJ102X; Mistral Part No: 110009030400-R; Package: 0402; Part_type: RESISTORS\FIXED; Project: HSE; RoHS: RoHS; Temperature: -55°C+155°C; Tolerance: 5%; Voltage: NA; Wattage: 1/10W; Weight: 0.8mg; Datasheet: Y:\MIS_DATABASE\DATASHEETS\RESISTORS\PAN-ERJSER_NOV17.PDF
R5694-R5696 = RESISTOR: RES 0E 1/20W 5% 0201; Chkd/date: NAVEED/301214; Crtd /date: MUDDU/120710; Custom_Duty: 15%; Customs_HS_Code: 85332119; Distributor_name: DIGIKEY; Distributor_part_number: 311-0.0NCT-ND; Footprint Path: Y:\MIS_DATABASE\Library\ALTIUM_TOOL\PCB_FOOTPRINTS\Altium_Footprint_Lib.PcbLib; Height: 0.26MM; Library Path: Y:\MIS_DATABASE\Library\ALTIUM_TOOL\SCHEMATICS_PARTS\MS_DISCRETE_Library.schlib; Mfr_name: YAGEO AMERICA; Mfr_part_number: RC0201JR-070RL; Mistral Part No: 110010070067-R; Package: 0201; Part_type: RESISTORS\FIXED; Project: PB_BUGBASE; RoHS: RoHS; SIGNAL_MODEL: RESISTOR_RES0201_0-5_0E_0E; Temperature: -55°C+125°C; Tolerance: 5%; Voltage: NA; Wattage: 1/20W; Weight: 0.17mg; Datasheet: Y:\MIS_DATABASE\DATASHEETS\RESISTORS\RCXXXXL-SER_MAR18.PDF
R5757 = RESISTOR: RES 0E 1/10W JUMPER 0402; Chkd/date: VASANTHA/061216; Crtd /date: NAVEED/201014; Custom_Duty: 15%; Customs_HS_Code: 85332119; Distributor_name: DIGIKEY; Distributor_part_number: P0.0JCT-ND; Footprint Path: Y:\MIS_DATABASE\Library\ALTIUM_TOOL\PCB_FOOTPRINTS\Altium_Footprint_Lib.PcbLib; Height: 0.40MM; IBISSP_MODLES: VALUE REPEATING 2 TIME; Library Path: Y:\MIS_DATABASE\Library\ALTIUM_TOOL\SCHEMATICS_PARTS\MS_DISCRETE_Library.schlib; Mfr_name: PANASONIC-ECG; Mfr_part_number: ERJ-2GE0R00X; Mistral Part No: 110018030052-R; Package: 0402; Part_type: RESISTORS\FIXED; Project: AEGIS POM; RoHS: RoHS; SIGNAL_MODEL: RESISTOR_RES0201_0-5_0E_0E; Temperature: -55°C+155°C; Tolerance: NA; Voltage: NA; Wattage: 1/10W; Weight: 0.8mg; Datasheet: Y:\MIS_DATABASE\DATASHEETS\RESISTORS\PAN-ERJSER_NOV17.PDF
RA3 RA4 RA8 RA9 = RESARR_ISO4: RES ARRAY 0E 31mW JUMPER 0201-4; Chkd/date: MANIRAJA/290918; Crtd /date: MANIRAJA/290918; Custom_Duty: 15%; Customs_HS_Code: 85332119; Distributor_name: DIGIKEY; Distributor_part_number: Y6000CT-ND; Footprint Path: Y:\MIS_DATABASE\Library\ALTIUM_TOOL\PCB_FOOTPRINTS\Altium_Footprint_Lib.PcbLib; Height: 0.45MM; Library Path: Y:\MIS_DATABASE\Library\ALTIUM_TOOL\SCHEMATICS_PARTS\MS_DISCRETE_Library.schlib; Manufacturer: PANASONIC-ECG; Mfr_name: PANASONIC-ECG; Mfr_part_number: EXB-18VR000X; Mistral Part No: 110018090033-R; Package: 0201-4; Part_type: RESISTORS\ARRAY; Project: TI_60GHz-AOP; RoHS: RoHS; SIGNAL_MODEL: RESARR_ISO4_RESA_EXB_0201-4_0-5_0E; Temperature: -55°C+125°C; Tolerance: NA; Voltage: NA; Wattage: 31mW; Weight: 1mg; Datasheet: Y:\MIS_DATABASE\DATASHEETS\RESISTORS\EXB-18V.PDF
U28 = S28HS512T_BGA24: IC 1.8V 512Mb SEMPER FLASH WITH OCTAL INTERFACE BGA24; Chkd/date: MANIRAJA/170120; Crtd /date: ALVY/170120; Custom_Duty: 15%; Customs_HS_Code: 85423100; Distributor_name: NA; Distributor_part_number: NA; Footprint Path: Y:\MIS_DATABASE\Library\ALTIUM_TOOL\PCB_FOOTPRINTS\Altium_Footprint_Lib.PcbLib; Height: 1.00MM; Library Path: Y:\MIS_DATABASE\Library\ALTIUM_TOOL\SCHEMATICS_PARTS\MS_MISCMEMORY_Library.schlib; Mfr_name: CYPRESS SEMICONDUCTOR; Mistral Part No: 141120010002; Package: BGA24; Part_type: ICS\DIGITAL\MEMORY; Project: J7VCL_SOM DUAL LEO PMIC; RoHS: NA; Temperature: -40°C+125°C; Tolerance: NA; Voltage: NA; Wattage: NA; Weight: NA; Datasheet: Y:\MIS_DATABASE\DATASHEETS\ICS\MEMORY\S28HS512T.PDF
C88 C504 C518 = CAP: CAP CERAMIC 2.2uF 25V 10% X5R AUTO 0402; Chkd/date: MANIRAJA/240920; Crtd /date: ALVY/240920; Custom_Duty: 15%; Customs_HS_Code: 85322990; Distributor_name: DIGIKEY; Distributor_part_number: 490-12267-1-ND; Footprint Path: Y:\MIS_DATABASE\Library\ALTIUM_TOOL\PCB_FOOTPRINTS\Altium_Footprint_Lib.PcbLib; Height: 0.70MM; Library Path: Y:\MIS_DATABASE\Library\ALTIUM_TOOL\SCHEMATICS_PARTS\MS_DISCRETE_Library.schlib; Mfr_name: MURATA; Mfr_part_number: GRT155R61E225KE13D; Mistral Part No: 120020090019-R; Package: 0402; Part_type: CAPACITORS\CERAMIC; Project: ECU_RO; RoHS: RoHS; Temperature: -55°C+85°C; Tolerance: 10%; Voltage: 25V; Wattage: NA; Weight: 0.65mg; Datasheet: Y:\MIS_DATABASE\DATASHEETS\CAPACITORS\GRT155R61E225KE13.PDF
C69 C527 = CAP: CAP CERAMIC 1uF 10V 20% X6S 0201; Chkd/date: PRADEEP/130623; Crtd /date: PRADEEP/130623; Custom_Duty: 15%; Customs_HS_Code: 85322990; Distributor_name: DIGIKEY; Distributor_part_number: 490-GRT033C81A105ME13DTR-ND; Footprint Path: Y:\MIS_DATABASE\Library\ALTIUM_TOOL\PCB_FOOTPRINTS\Altium_Footprint_Lib.PcbLib; Height: 0.39MM; Library Path: Y:\MIS_DATABASE\Library\ALTIUM_TOOL\SCHEMATICS_PARTS\MS_DISCRETE_Library.schlib; Mfr_name: MURATA; Mfr_part_number: GRT033C81A105ME13D; Mistral Part No: 120022060020-R; Package: 0201; Part_type: CAPACITORS\CERAMIC; Project: AM62P_SK; RoHS: RoHS; Temperature: -55°C+105°C; Tolerance: 20%; Voltage: 10V; Wattage: NA; Weight: NA; Datasheet: Y:\MIS_DATABASE\DATASHEETS\CAPACITORS\GRT033C81A105ME13D.PDF
R115 = RESISTOR: RES 100K 1/20W 5% 0201; Chkd/date: MANIRAJA/050517; Crtd /date: MANIRAJA/050517; Custom_Duty: 15%; Customs_HS_Code: 85332119; Distributor_name: DIGIKEY; Distributor_part_number: 311-100KNCT-ND; Footprint Path: Y:\MIS_DATABASE\Library\ALTIUM_TOOL\PCB_FOOTPRINTS\Altium_Footprint_Lib.PcbLib; Height: 0.26MM; Library Path: Y:\MIS_DATABASE\Library\ALTIUM_TOOL\SCHEMATICS_PARTS\MS_DISCRETE_Library.schlib; Mfr_name: YAGEO AMERICA; Mfr_part_number: RC0201JR-07100KL; Mistral Part No: 110009030176-R; Package: 0201; Part_type: RESISTORS\FIXED; Project: GOLDEN-I LITE; RoHS: RoHS; Temperature: -55°C+125°C; Tolerance: 5%; Voltage: NA; Wattage: 1/20W; Weight: 0.17mg; Datasheet: Y:\MIS_DATABASE\DATASHEETS\RESISTORS\RCXXXXL-SER_MAR18.PDF
TP21 TP116 = TESTPOINT: TESTPOINT CIR 20 SMD; Chkd/date: SHREESHAIL/171006; Crtd /date: MAZHAR/171006; Custom_Duty: NA; Customs_HS_Code: NA; Distributor_name: NA; Distributor_part_number: NA; Footprint Path: Y:\MIS_DATABASE\Library\ALTIUM_TOOL\PCB_FOOTPRINTS\Altium_Footprint_Lib.PcbLib; Height: NA; Library Path: Y:\MIS_DATABASE\Library\ALTIUM_TOOL\SCHEMATICS_PARTS\MS_DISCRETE_Library.schlib; MECHANICAL 3D STEP FILE: NA; Mfr_name: LOCAL; Mistral Part No: NA; Package: SMD; Project: BT MODULE_CSRBC04; RoHS: NA; Temperature: NA; Tolerance: NA; Voltage: NA; Wattage: NA; Weight: NA; Datasheet: NA
U49 = MTFC16GAPALBH_TFBGA153: IC 32GB e-MMC MEMORY VFBGA153; Chkd/date: PRAVEEN/010922; Crtd /date: PRAVEEN/010922; Custom_Duty: 15%; Customs_HS_Code: 85423100; Distributor_name: DIGIKEY; Distributor_part_number: 557-MTFC32GAZAQHD-IT-ND; Footprint Path: Y:\MIS_DATABASE\Library\ALTIUM_TOOL\PCB_FOOTPRINTS\Altium_Footprint_Lib.PcbLib; Height: 0.90MM; Library Path: Y:\MIS_DATABASE\Library\ALTIUM_TOOL\SCHEMATICS_PARTS\MS_MISCMEMORY_Library.schlib; Mfr_name: MICRON; Mistral Part No: 141122090001-R; Package: VFBGA153; Part_type: ICS\DIGITAL\MEMORY; Project: J7AHP_SK_BRD; RoHS: RoHS; Temperature: -40°C+95°C; Tolerance: NA; Voltage: NA; Wattage: NA; Weight: NA; Datasheet: Y:\MIS_DATABASE\DATASHEETS\ICS\MEMORY\MTFC64GAZAQHD-IT.PDF
C70 = CAP: CAP CERAMIC 220pF 50V 5% C0G(NP0) AUTO 0402; Chkd/date: PRADEEP/130623; Crtd /date: PRADEEP/130623; Custom_Duty: 15%; Customs_HS_Code: 85322990; Distributor_name: NA; Distributor_part_number: NA; Footprint Path: Y:\MIS_DATABASE\Library\ALTIUM_TOOL\PCB_FOOTPRINTS\Altium_Footprint_Lib.PcbLib; Height: 0.55MM; Library Path: Y:\MIS_DATABASE\Library\ALTIUM_TOOL\SCHEMATICS_PARTS\MS_DISCRETE_Library.schlib; Mfr_name: MURATA; Mfr_part_number: GRT1555C1H221JA02; Mistral Part No: 120022060024-R; Package: 0402; Part_type: CAPACITORS\CERAMIC; Project: AM62P_SK; RoHS: RoHS; Temperature: -55°C+125°C; Tolerance: 5%; Voltage: 50V; Wattage: NA; Weight: 3.1mg; Datasheet: Y:\MIS_DATABASE\DATASHEETS\CAPACITORS\GRT1555C1H221JA02.PDF
FL4 = EMIFILTER_IND: IND FERRITE BEAD CHIP 120E 2A 0402; Chkd/date: MANIRAJA/311221; Crtd /date: ALVY/301221; Custom_Duty: 24%; Customs_HS_Code: 85437099; Distributor_name: NA; Distributor_part_number: NA; Footprint Path: Y:\MIS_DATABASE\Library\ALTIUM_TOOL\PCB_FOOTPRINTS\Altium_Footprint_Lib.PcbLib; Height: 0.55MM; Library Path: Y:\MIS_DATABASE\Library\ALTIUM_TOOL\SCHEMATICS_PARTS\MS_FILTER_Library.schlib; Mfr_name: MURATA; Mfr_part_number: BLM15PX121SZ1B; Mistral Part No: 130021120017-R; Package: 0402; Part_type: INDUCTOR; Project: AM62Q_SKEVM_BRD; RoHS: RoHS; Temperature: -55°C+125°C; Tolerance: 25%; Voltage: NA; Wattage: NA; Weight: 1mg; Datasheet: Y:\MIS_DATABASE\DATASHEETS\DISCRETES\INDUCTORS\BLM-SER.PDF
J26 = CON_SDCARD9_MEM2075-00-140: CON MICROSD CARD 9POS FEMALE RT SMD; Chkd/date: PRADEEP/1812023; Crtd /date: TAMILARASU/181223; Custom_Duty: 24%; Customs_HS_Code: 85369090; Distributor_name: DIGIKEY; Distributor_part_number: 2073-MEM2052-00-195-00-ACT-ND; Footprint Path: Y:\MIS_DATABASE\Library\ALTIUM_TOOL\PCB_FOOTPRINTS\Altium_Footprint_Lib.PcbLib; Height: 1.95MM; Library Path: Y:\MIS_DATABASE\Library\ALTIUM_TOOL\SCHEMATICS_PARTS\MS_CONNECTOR_Library.schlib; Mfr_name: GCT; Mfr_part_number: MEM2052-00-195-00-A; Mistral Part No: 150023120024-R; Package: SMD; Part_type: CONNECTOR\MEMORY CARD; Project: AM62D_EVM; RoHS: RoHS; Temperature: -40°C+85°C; Tolerance: NA; Voltage: NA; Wattage: NA; Weight: NA; Datasheet: Y:\MIS_DATABASE\DATASHEETS\CONNECTORS\MEM2052-00-195-00-A.PDF
U2 = SN74LVC1G11DCKR_SC70-6: IC SINGLE 3-INPUT POSITIVE-AND GATE SON6; Chkd/date: MANIRAJA/270121; Crtd /date: ALVY/270121; Custom_Duty: 15%; Customs_HS_Code: 85423100; Distributor_name: DIGIKEY; Distributor_part_number: 296-30120-1-ND; Footprint Path: Y:\MIS_DATABASE\Library\ALTIUM_TOOL\PCB_FOOTPRINTS\Altium_Footprint_Lib.PcbLib; Height: 0.60MM; Library Path: Y:\MIS_DATABASE\Library\ALTIUM_TOOL\SCHEMATICS_PARTS\MS_GATE_Library.schlib; Mfr_name: TEXAS INSTRUMENTS; Mistral Part No: 141021010013-R; Package: SON6; Part_type: ICS\DIGITAL\GATES; Project: AM64X_SKEVM; RoHS: RoHS; Temperature: -40°C+125°C; Tolerance: NA; Voltage: NA; Wattage: NA; Weight: 33mg; Datasheet: Y:\MIS_DATABASE\DATASHEETS\ICS\DIGITAL\GATES\SN74LVC1G_NOV16.PDF
U4 = TPS22918DBVR_SOT23-6: IC ON RESISTANCE LOAD SWITCH SOT23-6; Automotive Alternate_mfr_name: TEXAS INSTRUMENTS; Automotive Alternate_mfr_part_number: TPS22918TDBVRQ1; Chkd/date: VASANTHA/130516; Crtd /date: VASANTHA/130516; Custom_Duty: 15%; Customs_HS_Code: 85423100; Distributor_name: DIGIKEY; Distributor_part_number: TPS22918DBVR-ND; Height: 1.45MM; Mfr_name: TEXAS INSTRUMENTS; Mistral Part No: 142016050007-R; Part_type: ICS\POWER; Project: TMDXCSK8127; RoHS: RoHS; Temperature: -40°C to 105°C; Tolerance: NA; Voltage: NA; Wattage: NA; Weight: NA; Datasheet: Y:\MIS_DATABASE\DATASHEETS\ICS\POWER\TPS22918DBV.PDF
U10 = TPD6E001RSE_UQFN10: IC 6CH ESD-PROTECTION ARRAY UQFN10; Chkd/date: USMAN/070612; Crtd /date: BAVISH/160811; Custom_Duty: 15%; Customs_HS_Code: 85423100; Distributor_name: DIGIKEY; Distributor_part_number: 296-21888-1-ND; Footprint Path: Y:\MIS_DATABASE\Library\ALTIUM_TOOL\PCB_FOOTPRINTS\Altium_Footprint_Lib.PcbLib; Height: 0.60MM; IBISSP_MODLES: Y:\MIS_DATABASE\IBIS\ICs\INTERFACE\TPD6E001RSE.IBS; Library Path: Y:\MIS_DATABASE\Library\ALTIUM_TOOL\SCHEMATICS_PARTS\MS_MISCINTERFACE_Library.schlib; Mfr_name: TEXAS INSTRUMENTS; Mistral Part No: 141011080020-R; Package: UQFN10; Part_type: ICS\INTERFACE; Project: DM385EVM_BASE-BOARD; RoHS: RoHS; Temperature: -40°C+85°C; Tolerance: NA; Voltage: NA; Wattage: NA; Weight: 7mg; Datasheet: Y:\MIS_DATABASE\DATASHEETS\ICS\INTERFACE\TPD6E001.PDF
U12 = TPD2E001DRLR_SOT-5: IC ESD-PROTECTION DIODE ARRAYS SOT-5; Chkd/date: NAVEED/150714; Crtd /date: MUDDU/250510; Custom_Duty: 15%; Customs_HS_Code: 85423100; Distributor_name: DIGIKEY; Distributor_part_number: 296-21883-1-ND; Footprint Path: Y:\MIS_DATABASE\Library\ALTIUM_TOOL\PCB_FOOTPRINTS\Altium_Footprint_Lib.PcbLib; Height: 0.60MM; Library Path: Y:\MIS_DATABASE\Library\ALTIUM_TOOL\SCHEMATICS_PARTS\MS_FILTER_Library.schlib; Mfr_name: TEXAS INSTRUMENTS; Mistral Part No: 140110060007-R; Package: SOT-5; Part_type: ICS\ANALOG\ACTIVE FILTER; Project: CENTAURUS; RoHS: RoHS; Temperature: -40°C+85°C; Tolerance: NA; Voltage: NA; Wattage: NA; Weight: 2.8mg; Datasheet: Y:\MIS_DATABASE\DATASHEETS\ICS\MISC\TPD2E001DRLR.PDF

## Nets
DGND: C28.2 C33.1 C37.2 C69.2 C70.2 C88.1 C93.1 C102.1 C103.1 C146.2 C148.2 C149.1 C388.2 C389.2 C390.2 C498.2 C503.2 C504.2 C514.2 C518.2 C520.2 C521.2 C527.2 C3705.2 C3706.1 C3707.2 C3708.2 C3709.2 J26.6(VSS) J26.SH1 J26.SH2 J26.SH3 J26.SH4 R202.2 R451.2 R504.2 R561.2 R562.2 R5709.2 R5754.1 R5820.1 R5821.1 R5822.2 R5823.1 U2.2(GND) U4.2(GND) U10.5(GND) U12.4(GND) U26.3(GND) U27.3(GND) U28.B3(VSS) U28.C1(VSSQ) U28.E5(VSSQ) U49.A6(VSS) U49.C4(VSSQ) U49.E7(VSS) U49.G5(VSS) U49.H10(VSS) U49.J5(VSS) U49.K8(VSS) U49.N2(VSSQ) U49.N5(VSSQ) U49.P4(VSSQ) U49.P6(VSSQ) U140.B3(VSS) U140.C1(VSSQ) U140.E5(VSSQ) U2348.3(GND) ; also on sheet 1 2 12 13 14 15 16 17 18 19 20 21 22 23 24 25 31 32 33 34 35 36 37 38 39 40 41 42 43 44 45 46 47 48 49 50 51 52 53 54 55 56
VCC1V8_SYS: C37.1 C102.2 C146.1 C148.1 C149.2 C388.1 C389.1 C390.1 C503.1 C514.1 C518.1 C3705.1 C3706.2 C3707.1 C3708.1 C3709.1 R17.2 R18.2 R70.2 R115.1 R117.1 R122.2 R123.2 R124.2 R262.1 R263.1 R264.1 R266.1 R267.1 R269.1 R270.1 R275.1 R443.2 R444.2 R445.2 R446.2 R447.2 R448.2 R449.2 R450.2 R452.2 R454.2 R565.1 R575.1 R5213.2 R5693.2 R5698.2 R5699.2 R5710.2 R5711.2 R5712.2 R5713.2 R5714.2 R5715.2 R5716.2 R5717.2 R5753.2 R5810.2 U2.5(VCC) U12.1(VCC) U26.5(VCC) U27.5(VCC) U28.B4(VCC) U28.D1(VCCQ) U28.E4(VCCQ) U49.C6(VCCQ) U49.M4(VCCQ) U49.N4(VCCQ) U49.P3(VCCQ) U49.P5(VCCQ) U140.B4(VCC) U140.D1(VCCQ) U140.E4(VCCQ) U2348.5(VCC) ; also on sheet 16 21 22 23 24 31 34 38 39 40 42 43 44 46 47 48 52 54 56
VCC_3V3_SYS: C28.1 C33.2 C498.1 C504.1 C520.1 U4.1(VIN) U49.E6(VCC) U49.F5(VCC) U49.J10(VCC) U49.K9(VCC) ; also on sheet 1 2 12 16 17 23 31 34 35 36 38 40 44 47 48 49 50 55 56
VDD_MMC0: C69.1 FL4.1 U4.5(QOD) U4.6(VOUT)
VDD_MMC0_SD: C88.2 C93.2 FL4.2 J26.4(VDD) TP21.1(TP)
VDDIM: C521.1 C527.1 U49.C2(VDDIM)
VDDSHV_SDIO: C103.2 R54.2 R55.2 R57.2 R64.2 R65.2 R66.2 U10.10(VCC) ; also on sheet 16 20
AEC1_GPIO0_1: R5757.2 ; also on sheet 42
eMMC_CLK: R561.1 R565.2 U49.M6(CLK) ; also on sheet 2
eMMC_CMD: R575.2 U49.M5(CMD) ; also on sheet 2
eMMC_D0: R269.2 U49.A3(DAT0) ; also on sheet 2
eMMC_D1: R266.2 U49.A4(DAT1) ; also on sheet 2
eMMC_D2: R263.2 U49.A5(DAT2) ; also on sheet 2
eMMC_D3: R275.2 U49.B2(DAT3) ; also on sheet 2
eMMC_D4: R270.2 U49.B3(DAT4) ; also on sheet 2
eMMC_D5: R267.2 U49.B4(DAT5) ; also on sheet 2
eMMC_D6: R264.2 U49.B5(DAT6) ; also on sheet 2
eMMC_D7: R262.2 U49.B6(DAT7) ; also on sheet 2
eMMC_RSTn: R117.2 R5822.1 U26.4(Y) U49.K5(RST_N)
GPIO_eMMC_RSTn: R116.1 ; also on sheet 47
GPIO_HYPERRAM_RSTn: R5697.1 U136.C12(OSPI1_CSn1)
HYPERBUS0_CK: R5694.1 R5754.2 U140.B2(CK)
HYPERBUS0_CK#: R5695.1 R5753.1 U140.B1(CK#)
HYPERBUS0_CS#: R5693.1 R5696.1 U140.A3(CS#)
HYPERBUS0_DQ0: R5715.1 RA8.1 U140.D3(DQ0)
HYPERBUS0_DQ1: R5716.1 RA8.2 U140.D2(DQ1)
HYPERBUS0_DQ2: R5712.1 RA8.4 U140.C4(DQ2)
HYPERBUS0_DQ3: R5710.1 RA8.3 U140.D4(DQ3)
HYPERBUS0_DQ4: R5717.1 RA9.1 U140.D5(DQ4)
HYPERBUS0_DQ5: R5714.1 RA9.4 U140.E3(DQ5)
HYPERBUS0_DQ6: R5713.1 RA9.2 U140.E2(DQ6)
HYPERBUS0_DQ7: R5711.1 RA9.3 U140.E1(DQ7)
HYPERBUS0_RST#: R5698.1 R5820.2 U140.A4(RESET#) U2348.4(Y)
HYPERBUS0_RWDS: R5709.1 R5752.1 R5810.1 U136.B15(OSPI1_DQS)
MMC0_SD_EN: R21.1 ; also on sheet 47
MMC0_SD_LS_EN: R17.1 R5823.2 U2.4(Y) U4.3(ON)
OSPI0_CSN0: R206.2 U136.A17(OSPI0_CSn0)
OSPI0_RESET_OUT0: R121.1 U136.A16(OSPI0_CSn3)
OSPI_CLK: R197.1 R451.1 U28.B2(CK)
OSPI_CS: R206.1 R447.1 R5826.2 R5827.2
OSPI_DQ0: R446.1 RA3.1 U28.D3(DQ0)
OSPI_DQ1: R450.1 RA3.2 U28.D2(DQ1)
OSPI_DQ2: R452.1 RA3.3 U28.C4(DQ2)
OSPI_DQ3: R449.1 RA3.4 U28.D4(DQ3)
OSPI_DQ4: R448.1 RA4.1 U28.D5(DQ4)
OSPI_DQ5: R445.1 RA4.2 U28.E3(DQ5)
OSPI_DQ6: R444.1 RA4.3 U28.E2(DQ6)
OSPI_DQ7: R443.1 RA4.4 U28.E1(DQ7)
OSPI_DQS: R453.1 U28.C3(DS)
OSPI_DQS_SOC: R453.2 R454.1 R504.1 U136.B19(OSPI0_DQS)
OSPI_INTn: R123.1 R125.1
OSPI_RSTn: R124.1 R5821.2 U27.4(Y) U28.A4(RESET#)
RESETSTATZ_1V8: U2.3(B) U26.2(B) U27.2(B) U2348.2(B) ; also on sheet 22 23 40 41 42 43 46 47
SD_MMC0_CLK: J26.5(CLK) R54.1 R202.1 U10.6(IO4) ; also on sheet 2
SD_MMC0_CMD: J26.3(CMD) R66.1 U10.1(IO1) ; also on sheet 2
SD_MMC0_D0: J26.7(DAT0) R65.1 U10.8(IO6) ; also on sheet 2
SD_MMC0_D1: J26.8(DAT1) R57.1 U10.7(IO5) ; also on sheet 2
SD_MMC0_D2: J26.1(DAT2) R64.1 U10.2(IO2) ; also on sheet 2
SD_MMC0_D3: J26.2(CD/DAT3) R55.1 U10.3(IO3) ; also on sheet 2
SD_MMC0_SDCD: J26.9(CD) R70.1 U12.5(IO2) ; also on sheet 31
SOC_HYPERBUS0_DQ0: RA8.8 U136.A13(OSPI1_D0)
SOC_HYPERBUS0_DQ1: RA8.7 U136.D12(OSPI1_D1)
SOC_HYPERBUS0_DQ2: RA8.5 U136.D13(OSPI1_D2)
SOC_HYPERBUS0_DQ3: RA8.6 U136.C13(OSPI1_D3)
SOC_HYPERBUS0_DQ4: RA9.8 U136.A15(OSPI1_D4)
SOC_HYPERBUS0_DQ5: RA9.5 U136.C15(OSPI1_D5)
SOC_HYPERBUS0_DQ6: RA9.7 U136.B14(OSPI1_D6)
SOC_HYPERBUS0_DQ7: RA9.6 U136.C14(OSPI1_D7)
SoC_OSPI_CLK: R197.2 U136.B17(OSPI0_CLK)
SoC_OSPI_DQ0: RA3.8 U136.B16(OSPI0_D0)
SoC_OSPI_DQ1: RA3.7 U136.D17(OSPI0_D1)
SoC_OSPI_DQ2: RA3.6 U136.C17(OSPI0_D2)
SoC_OSPI_DQ3: RA3.5 U136.D16(OSPI0_D3)
SoC_OSPI_DQ4: RA4.8 U136.E16(OSPI0_D4)
SoC_OSPI_DQ5: RA4.7 U136.B18(OSPI0_D5)
SoC_OSPI_DQ6: RA4.6 U136.D18(OSPI0_D6)
SoC_OSPI_DQ7: RA4.5 U136.C18(OSPI0_D7)
SPI1_CS1: U136.D15(OSPI0_CSn2) ; also on sheet 43
N16878497: R562.1 TP116.1(TP) U49.H5(DS)
N16880083: R18.1 R21.2 U2.1(A)
N16956459: R121.2 R122.1 U27.1(A)
N24478126: C70.1 U4.4(CT)
N27148451: R125.2 U28.A5(INT#)
N27995683: R5752.2 U140.C3(RWDS)
N28038972: R5213.1 U2.6(C)
N28088261: R5694.2 U136.A14(OSPI1_CLK)
N28088302: R5695.2 U136.B13(OSPI1_LBCLKO)
N28088339: R5696.2 U136.B12(OSPI1_CSn0)
N28088462: R5697.2 R5699.1 U2348.1(A)
N28268314: R5757.1 U136.C16(OSPI0_CSn1)
N28271262: R115.2 R116.2 U26.1(A)
N29295413: R5826.1 U28.C2(CS#)
N29295438: R5827.1 U28.A3(DNU2)

Not connected (* = marked no-connect by the designer): U10 4(NC1)* 9(NC2)*; U12 2(NC)* 3(IO1)*; U28 A2(DNU1)* B1(DNU3)* B5(DNU4)* C5(DNU5)*; U49 A1(NC1)* A2(NC2)* A7(RFU1)* A8(NC3)* A9(NC4)* A10(NC5)* A11(NC6)* A12(NC7)* A13(NC8)* A14(NC9)* B1(NC10)* B7(NC11)* B8(NC12)* B9(NC13)* B10(NC14)* B11(NC15)* B12(NC16)* B13(NC17)* B14(NC18)* C1(NC19)* C3(NC20)* C5(NC21)* C7(NC22)* C8(NC23)* C9(NC24)* C10(NC25)* C11(NC26)* C12(NC27)* C13(NC28)* C14(NC29)* D1(NC30)* D2(NC31)* D3(NC32)* D4(NC33)* D12(NC34)* D13(NC35)* D14(NC36)* E1(NC37)* E2(NC38)* E3(NC39)* E5(RFU2)* E8(VSF1)* E9(VSF2)* E10(VSF3)* E12(NC40)* E13(NC41)* E14(NC42)* F1(NC43)* F2(NC44)* F3(NC45)* F10(VSF4)* F12(NC46)* F13(NC47)* F14(NC48)* G1(NC49)* G2(NC50)* G3(NC51)* G10(VSF5)* G12(NC52)* G13(NC53)* G14(NC54)* H1(NC55)* H2(NC56)* H3(NC57)* H12(NC58)* H13(NC59)* H14(NC60)* J1(NC61)* J2(NC62)* J3(NC63)* J12(NC64)* J13(NC65)* J14(NC66)* K1(NC67)* K2(NC68)* K3(NC69)* K6(RFU3)* K7(RFU4)* K10(VSF6)* K12(NC70)* K13(NC71)* K14(NC72)* L1(NC73)* L2(NC74)* L3(NC75)* L12(NC76)* L13(NC77)* L14(NC78)* M1(NC79)* M2(NC80)* M3(NC81)* M7(NC82)* M8(NC83)* M9(NC84)* M10(NC85)* M11(NC86)* M12(NC87)* M13(NC88)* M14(NC89)* N1(NC90)* N3(NC91)* N6(NC92)* N7(NC93)* N8(NC94)* N9(NC95)* N10(NC96)* N11(NC97)* N12(NC98)* N13(NC99)* N14(NC100)* P1(NC101)* P2(NC102)* P7(NC103)* P8(NC104)* P9(NC105)* P10(VSF7)* P11(NC106)* P12(NC107)* P13(NC108)* P14(NC109)*; U136 A18(OSPI0_LBCLKO)*; U140 A2(RFU_1)* A5(RFU_2)* B5(RFU_3)* C2(RFU_4)* C5(RFU_5)*

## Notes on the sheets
sheet 26
- HYPERRAM DEVICE
- 100E
- HYPERRAM RESET
sheet 27
- OSPI INTERFACE
- D-Note :
  Recommended 0E provision on
  OSPI0 clock for signal integrity
- Place RA3 & RA4 closer to SoC
- D-Note :
  These series resistors are for enabling OSPI
  These are specific to SK and optional if the interface is fixed
- GPIO0_12
- Note: Pullup is DNI
- Place R453 close
  to the Memory
- Place  R504 closer
  to the SoC
- Note: Pullup is DNI
- Place R5709 closer
  to the SoC
- OSPI  FLASH
- OSPI  FLASH RESET
- D-Note :
  SoC Internal pulls are off during power-up.
  External pullups are recommended near to the attached device
- Silk: OSPI FLASH
- NOTE:
  OSPI NAND Flash can be replaced with the Footprint
  compatible OCTAL NOR Flash (Mfr Part# W35N01JWTBAG)
sheet 28
- eMMC FLASH
- External pulls for MMC0 are optional and DNI
  Internal Pulls are enabled by default
  for the MMC0 interface
- eMMC FLASH RESET
- The ANDing logic includes 2 functions
  1. I/O Level translation
  2. GPIO reset
  Verify I/O compatibility before optimizing
- Design Note: eMMC_RSTn Active low
  s/w control
sheet 29
- SD CARD INTERFACE
- SD CARD RESET
- LOAD SWITCH
- Note: MMC0_CLK pullup is a DNI
- Place near SD Card Connector
